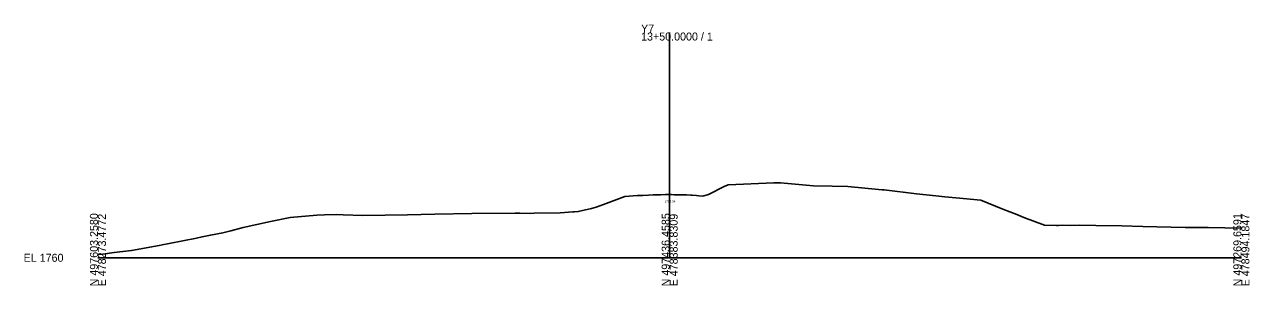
# Model space of a CAD drawing. Extents: x -26 to 403, y -10 to 4071.
# Drawn here: x -25.7 to 402.8, y 3490.3 to 3581.6 of the extents above; entities that cross this region are included whole.
import ezdxf

# ---------------------------------------------------------------- set-up
doc = ezdxf.new("R2010")
doc.units = 0
for name, color, linetype in [('Exist Cross Section Cell', 7, 'Continuous'), ('Exist XS Center Line Elevation Label', 7, 'Continuous'), ('Exist XS Ground Line', 7, 'Continuous'), ('Scratch_Level_5', 7, 'Continuous')]:
    doc.layers.add(name, color=color, linetype=linetype)

msp = doc.modelspace()

# ---------------------------------------------------------------- linework, layer by layer
at = {"layer": 'Exist Cross Section Cell'}
for p, q in [((200, 3500), (200, 3578.8)), ((0, 3500), (200, 3500)), ((200, 3500), (400, 3500))]:
    msp.add_line(p, q, dxfattribs=at)
at = {"layer": 'Exist XS Ground Line'}
msp.add_lwpolyline([(0, 3501.18), (1.71, 3501.31), (5.68, 3501.86), (11.68, 3502.55), (21.39, 3504.32), (22.48, 3504.54), (24.94, 3505.03), (34.48, 3506.92), (36.42, 3507.33), (39.35, 3507.92), (43.64, 3508.74), (46.47, 3509.46), (50.85, 3510.56), (60.39, 3512.66), (67.25, 3514.09), (76.54, 3514.85), (79.29, 3515.01), (83.43, 3515.09), (85.82, 3514.99), (92.66, 3514.77), (108.31, 3515.08), (117.9, 3515.28), (130.75, 3515.49), (145.93, 3515.59), (146.66, 3515.59), (147, 3515.59), (147.56, 3515.6), (151.07, 3515.54), (152.55, 3515.6), (161.7, 3515.68), (166.15, 3516.03), (166.76, 3516.07), (168, 3516.17), (172.63, 3517.2), (174.24, 3517.74), (176.86, 3518.64), (184.29, 3521.41), (188.75, 3521.74), (190.66, 3521.81), (192.57, 3521.91), (194.28, 3522), (195.58, 3522.04), (196.85, 3522.06), (198.55, 3522.08), (200.03, 3522.08), (200.6, 3522.08), (201.54, 3522.07), (201.89, 3522.06), (204.53, 3522.02), (205.85, 3522), (207.42, 3521.93), (207.82, 3521.89), (209.43, 3521.75), (210.15, 3521.69), (211.49, 3521.57), (211.97, 3521.68), (213.63, 3522.12), (219.03, 3524.89), (220.5, 3525.57), (236.43, 3526.19), (238.35, 3526.27), (238.75, 3526.24), (250.35, 3525.13), (256.88, 3525.02), (262.34, 3524.98), (273.02, 3523.93), (274.33, 3523.81), (275.01, 3523.74), (286.33, 3522.35), (293.13, 3521.7), (296.25, 3521.36), (302.62, 3520.74), (308.89, 3520.15), (316.57, 3516.95), (321.49, 3515.1), (323.87, 3514.07), (331.11, 3511.36), (335.3, 3511.33), (336.05, 3511.34), (337.34, 3511.36), (340.13, 3511.35), (343.36, 3511.39), (349.03, 3511.31), (358.13, 3511.12), (365.47, 3510.97), (380.38, 3510.65), (387.6, 3510.61), (388.35, 3510.6), (394.19, 3510.51), (400, 3510.39)], dxfattribs=at)
at = {"layer": 'Scratch_Level_5'}
msp.add_lwpolyline([(0, 3501.18), (1.71, 3501.31), (5.68, 3501.86), (11.68, 3502.55), (21.39, 3504.32), (22.48, 3504.54), (24.94, 3505.03), (34.48, 3506.92), (36.42, 3507.33), (39.35, 3507.92), (43.64, 3508.74), (46.47, 3509.46), (50.85, 3510.56), (60.39, 3512.66), (67.25, 3514.09), (76.54, 3514.85), (79.29, 3515.01), (83.43, 3515.09), (85.82, 3514.99), (92.66, 3514.77), (108.31, 3515.08), (117.9, 3515.28), (130.75, 3515.49), (145.93, 3515.59), (146.66, 3515.59), (147, 3515.59), (147.56, 3515.6), (151.07, 3515.54), (152.55, 3515.6), (161.7, 3515.68), (166.15, 3516.03), (166.76, 3516.07), (168, 3516.17), (172.63, 3517.2), (174.24, 3517.74), (176.86, 3518.64), (184.29, 3521.41), (188.75, 3521.74), (190.66, 3521.81), (192.57, 3521.91), (194.28, 3522), (195.58, 3522.04), (196.85, 3522.06), (198.55, 3522.08), (200.03, 3522.08), (200.6, 3522.08), (201.54, 3522.07), (201.89, 3522.06), (204.53, 3522.02), (205.85, 3522), (207.42, 3521.93), (207.82, 3521.89), (209.43, 3521.75), (210.15, 3521.69), (211.49, 3521.57), (211.97, 3521.68), (213.63, 3522.12), (219.03, 3524.89), (220.5, 3525.57), (236.43, 3526.19), (238.35, 3526.27), (238.75, 3526.24), (250.35, 3525.13), (256.88, 3525.02), (262.34, 3524.98), (273.02, 3523.93), (274.33, 3523.81), (275.01, 3523.74), (286.33, 3522.35), (293.13, 3521.7), (296.25, 3521.36), (302.62, 3520.74), (308.89, 3520.15), (316.57, 3516.95), (321.49, 3515.1), (323.87, 3514.07), (331.11, 3511.36), (335.3, 3511.33), (337.34, 3511.36)], dxfattribs=at)

# ---------------------------------------------------------------- texts
at = {"layer": 'Exist Cross Section Cell'}
for s, p in [('Y7', (190, 3578.8)), ('13+50.0000 / 1', (190, 3576)), ('EL 1760', (-26, 3498.6))]:
    msp.add_text(s, height=2.8, dxfattribs=at).set_placement(p)
for s, p in [('N 497603.2580', (0, 3490)), ('E 478273.4772', (2.8, 3490)), ('N 497436.4585', (200, 3490)), ('E 478383.8309', (202.8, 3490)), ('N 497269.6591', (400, 3490)), ('E 478494.1847', (402.8, 3490))]:
    msp.add_text(s, height=2.8, rotation=90, dxfattribs=at).set_placement(p)
at = {"layer": 'Exist XS Center Line Elevation Label'}
msp.add_text('1782.08', height=0.75, dxfattribs=at).set_placement((198.24, 3519.33))

doc.saveas('drawing.dxf')
